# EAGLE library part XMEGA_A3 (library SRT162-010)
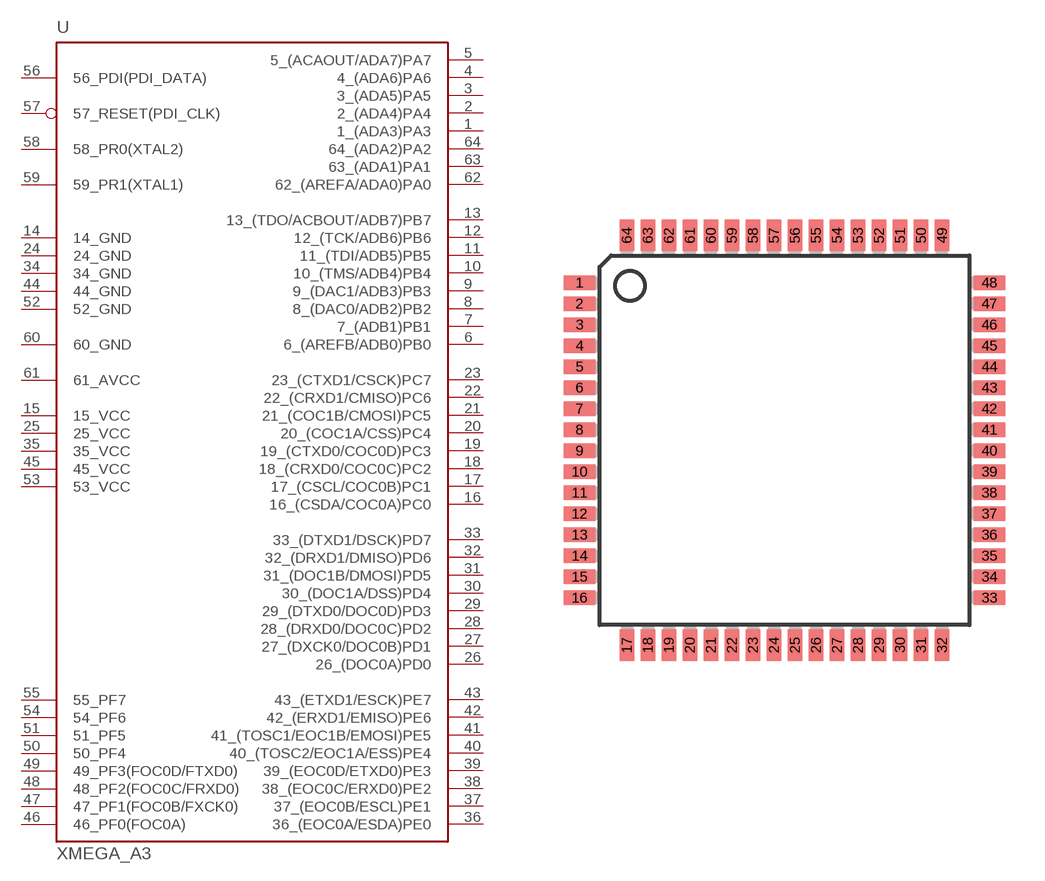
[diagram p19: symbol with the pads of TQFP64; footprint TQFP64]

Designator prefix U

## XMEGA_A3  [TQFP64]
1  1_(ADA3)PA3
2  2_(ADA4)PA4
3  3_(ADA5)PA5
4  4_(ADA6)PA6
5  5_(ACAOUT/ADA7)PA7
6  6_(AREFB/ADB0)PB0
7  7_(ADB1)PB1
8  8_(DAC0/ADB2)PB2
9  9_(DAC1/ADB3)PB3
10  10_(TMS/ADB4)PB4
11  11_(TDI/ADB5)PB5
12  12_(TCK/ADB6)PB6
13  13_(TDO/ACBOUT/ADB7)PB7
14  14_GND
15  15_VCC
16  16_(CSDA/COC0A)PC0
17  17_(CSCL/COC0B)PC1
18  18_(CRXD0/COC0C)PC2
19  19_(CTXD0/COC0D)PC3
20  20_(COC1A/CSS)PC4
21  21_(COC1B/CMOSI)PC5
22  22_(CRXD1/CMISO)PC6
23  23_(CTXD1/CSCK)PC7
24  24_GND
25  25_VCC
26  26_(DOC0A)PD0
27  27_(DXCK0/DOC0B)PD1
28  28_(DRXD0/DOC0C)PD2
29  29_(DTXD0/DOC0D)PD3
30  30_(DOC1A/DSS)PD4
31  31_(DOC1B/DMOSI)PD5
32  32_(DRXD1/DMISO)PD6
33  33_(DTXD1/DSCK)PD7
34  34_GND
35  35_VCC
36  36_(EOC0A/ESDA)PE0
37  37_(EOC0B/ESCL)PE1
38  38_(EOC0C/ERXD0)PE2
39  39_(EOC0D/ETXD0)PE3
40  40_(TOSC2/EOC1A/ESS)PE4
41  41_(TOSC1/EOC1B/EMOSI)PE5
42  42_(ERXD1/EMISO)PE6
43  43_(ETXD1/ESCK)PE7
44  44_GND
45  45_VCC
46  46_PF0(FOC0A)
47  47_PF1(FOC0B/FXCK0)
48  48_PF2(FOC0C/FRXD0)
49  49_PF3(FOC0D/FTXD0)
50  50_PF4
51  51_PF5
52  52_GND
53  53_VCC
54  54_PF6
55  55_PF7
56  56_PDI(PDI_DATA)
57  57_RESET(PDI_CLK)
58  58_PR0(XTAL2)
59  59_PR1(XTAL1)
60  60_GND
61  61_AVCC
62  62_(AREFA/ADA0)PA0
63  63_(ADA1)PA1
64  64_(ADA2)PA2

## Footprint TQFP64 (pad centres in mm)
smd 1.194 x 0.559: 1 -7.8,6; 2 -7.8,5.2; 3 -7.8,4.4; 4 -7.8,3.6; 5 -7.8,2.8; 6 -7.8,2; 7 -7.8,1.2; 8 -7.8,0.4; 9 -7.8,-0.4; 10 -7.8,-1.2; 11 -7.8,-2; 12 -7.8,-2.8; 13 -7.8,-3.6; 14 -7.8,-4.4; 15 -7.8,-5.2; 16 -7.8,-6; 33 7.8,-6; 34 7.8,-5.2; 35 7.8,-4.4; 36 7.8,-3.6; 37 7.8,-2.8; 38 7.8,-2; 39 7.8,-1.2; 40 7.8,-0.4; 41 7.8,0.4; 42 7.8,1.2; 43 7.8,2; 44 7.8,2.8; 45 7.8,3.6; 46 7.8,4.4; 47 7.8,5.2; 48 7.8,6
smd 0.559 x 1.194: 17 -6,-7.8; 18 -5.2,-7.8; 19 -4.4,-7.8; 20 -3.6,-7.8; 21 -2.8,-7.8; 22 -2,-7.8; 23 -1.2,-7.8; 24 -0.4,-7.8; 25 0.4,-7.8; 26 1.2,-7.8; 27 2,-7.8; 28 2.8,-7.8; 29 3.6,-7.8; 30 4.4,-7.8; 31 5.2,-7.8; 32 6,-7.8; 49 6,7.8; 50 5.2,7.8; 51 4.4,7.8; 52 3.6,7.8; 53 2.8,7.8; 54 2,7.8; 55 1.2,7.8; 56 0.4,7.8; 57 -0.4,7.8; 58 -1.2,7.8; 59 -2,7.8; 60 -2.8,7.8; 61 -3.6,7.8; 62 -4.4,7.8; 63 -5.2,7.8; 64 -6,7.8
